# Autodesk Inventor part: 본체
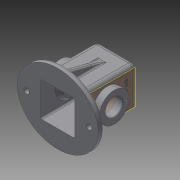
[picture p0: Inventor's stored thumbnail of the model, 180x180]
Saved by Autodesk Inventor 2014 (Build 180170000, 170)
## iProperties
Created: 2017-07
Part Number: 본체
Material: 일반
Document SubType Name: Modeling
Designer: 406-3333
Density: 1 g/cm^3
Appearance: 기본값
Author: 406-3333
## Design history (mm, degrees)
sketch "스케치1" dims "d0" = 65, "d1" = 75
  geometry: 2 further points; 1 other entity
  constraints: 1 coincident, 2 other
extrude "돌출1" new body sketch "스케치1" distance "d2" = 10; taper "d3" = 0 deg
sketch "스케치2"
  geometry: L1 (37, 37)-(-37, 37); L2 (-37, 37)-(-37, -37); L3 (-37, -37)-(37, -37); L4 (37, -37)-(37, 37); L5 (37, 37)-(-37, -37); L6 (-37, 37)-(37, -37); 1 further point; 1 other entity
  constraints: 12 end point, 2 midpoint, 2 parallel, 1 horizontal, 1 perpendicular, 1 other
  dimensions: "d4" = 74 distance between parallel lines of L4 L2; "d5" = 74 distance between parallel lines of L3 L1
extrude "돌출2" join sketch "스케치2" distance "d6" = 100; taper "d7" = 0 deg
node "작업 평면1"
sketch "스케치4"
  geometry: L1 (102, 0)-(102, -10) reference; L2 (102, -10)-(-28, -10) reference; L3 (-28, -10)-(-28, 0) reference; L4 (-28, 0)-(0, 0) reference; L5 (0, 0)-(0, 100) reference; L6 (0, 100)-(74, 100) reference; L7 (74, 100)-(74, 0) reference; L8 (74, 0)-(102, 0) reference; L9 (-18, 0)-(0, 72.194); L10 (74, 72.194)-(92, 0); L11 (-18, 0)-(0, 0); L12 (74, 72.194)-(74, 0); 1 further point
  constraints: 8 end point, 4 point on line, 1 collinear, 1 perpendicular
  dimensions: "d12" = 14 deg angle of L9 L3; "d13" = 14 deg angle of L1 L10; "d14" = 10 distance from line of L9.start L3; "d15" = 10 distance of L1.start L10.end
extrude "돌출4" join sketch "스케치4" stored distance "d16" = 10; taper "d17" = 0 deg
node "작업 평면2"
node "작업 평면4"
  node "작업 평면3"
sketch "스케치8"
  geometry: L1 (-11.448, 0)-(85.448, 0) reference; L2 (85.448, 0)-(85.448, -10) reference; L3 (85.448, -10)-(-11.448, -10) reference; L4 (-11.448, -10)-(-11.448, 0) reference; L5 (37, -10)-(37, 119.133); C1 r 27.5 at (37, 45)
  constraints: 2 end point, 1 centre point, 1 parallel, 1 point on line
  dimensions: "d29" = 55 distance from line of L3 C1.centre; "d30" = 55 diameter of C1
extrude "돌출8" join sketch "스케치8" distance "d31" = 100; taper "d32" = 0 deg
node "작업 평면5"
hole "구멍1" diameter "d45" = 32; stored, may be unused: countersink angle "d49" = 90 deg, drill point angle "d51" = 118 deg; dims "d43" = 10, "d44" = 10, "d46" = 6, "d47" = 4, "d48" = 2, "d50" = 8
sketch "스케치11" dims "d59" = 45
  geometry: L1 (0, 0)-(0, 47.659); C1 r 27.5 at (0, 0) reference; 3 further points
  constraints: 2 end point, 1 coincident, 1 point on line, 1 vertical, 1 vertical alignment, 2 other
hole "구멍3" sketch "스케치11" at (0, 22.5) diameter "d60" = 3.242; stored, may be unused: countersink angle "d64" = 90 deg, drill point angle "d66" = 118 deg; dims "d61" = 8, "d62" = 28, "d63" = 4, "d65" = 10
node "작업 평면6"
fillet "모깎기1" dims "d70" = 8
fillet "모깎기2" dims "d71" = 8
fillet "모깎기3" dims "d72" = 0.5
node "작업 평면7"
sketch "스케치12"
  geometry: L1 (20, 20)-(-20, 20); L2 (-20, 20)-(-20, -20); L3 (-20, -20)-(20, -20); L4 (20, -20)-(20, 20); L5 (20, 20)-(-20, -20); L6 (-20, 20)-(20, -20); 1 further point
  constraints: 12 end point, 2 midpoint, 2 parallel, 1 horizontal, 1 perpendicular
  dimensions: "d77" = 40 distance between parallel lines of L4 L2; "d78" = 40 distance between parallel lines of L3 L1
node "작업 평면8"
extrude "돌출10" join sketch "스케치12" distance "d84" = 10; taper "d85" = 0 deg
fillet "모깎기7" dims "d86" = 3
fillet "모깎기8" dims "d87" = 3
node "작업 평면9"
sketch "스케치14"
  geometry: 2 further points
  constraints: 1 coincident
hole "구멍4" sketch "스케치14" at (0, 0) diameter "d89" = 21; stored, may be unused: countersink angle "d93" = 90 deg, drill point angle "d95" = 118 deg; dims "d90" = 8, "d91" = 28, "d92" = 4, "d94" = 10
chamfer "모따기1" distance "d96" = 1; stored, may be unused: second distance "d97" = 2, angle "d98" = 5 deg
node "작업 평면10"
sketch "스케치15"
  geometry: L1 (12, 18)-(46, 18) reference; L2 (66, -92)-(66, 0) reference; 3 further points
  constraints: 1 other
  dimensions: "d101" = 30 distance from line of point (29, -12) L1; "d102" = 37 distance from line of L2 point (29, -12)
feature "엠보싱1" sketch "스케치15" dims "d103" = 0.5, "d104" = 0
fillet "모깎기10" dims "d105" = 3
fillet "모깎기11" dims "d106" = 3
fillet "모깎기12" dims "d107" = 3
sketch "스케치13"
  geometry: L1 (-72, 0)-(72, 0); L2 (-5, -37)-(-29, -37) reference; L3 (-37, -29)-(-37, 29) reference; L4 (-29, 37)-(-5, 37) reference; L5 (-5, 37)-(-5, 55) reference; L6 (-5, 55)-(5, 55) reference; L7 (5, 55)-(5, 37) reference; L8 (5, 37)-(29, 37) reference; L9 (37, 29)-(37, -29) reference; L10 (29, -37)-(5, -37) reference; L11 (5, -37)-(5, -55) reference; L12 (5, -55)-(-5, -55) reference; L13 (-5, -55)-(-5, -37) reference; C1 r 5 at (-58, 0); C2 r 5 at (58, 0); A1 r 8 centre (-29, -29) between (-37, -29) and (-29, -37) reference; A2 r 8 centre (-29, 29) between (-29, 37) and (-37, 29) reference; A3 r 8 centre (29, 29) between (37, 29) and (29, 37) reference; A4 r 8 centre (29, -29) between (29, -37) and (37, -29) reference; 2 further points; 1 other entity
  constraints: 2 centre point, 2 end point, 2 point on line, 1 other
  dimensions: "d80" = 58 distance of point (0, 0) C1.centre; "d81" = 58 distance of point (0, 0) C2.centre; "d82" = 10 diameter of C1; "d83" = 10 diameter of C2
extrude "돌출11" cut sketch "스케치13" stored distance "d108" = 10; taper "d109" = 0 deg
sketch "스케치16"
  geometry: L1 (32, 32)-(-32, 32); L2 (-32, 32)-(-32, -32); L3 (-32, -32)-(32, -32); L4 (32, -32)-(32, 32); L5 (32, 32)-(-32, -32); L6 (-32, 32)-(32, -32); C1 r 10.5 at (0, 0) reference; 1 further point; 1 other entity
  constraints: 12 end point, 2 midpoint, 2 parallel, 1 horizontal, 1 perpendicular, 1 other
  dimensions: "d110" = 64 distance of L3.end L2.end; "d111" = 64 distance of L2.end L1.end
extrude "돌출12" cut sketch "스케치16" distance "d112" = 105; taper "d113" = 0 deg
fillet "모깎기13" dims "d114" = 3
node "작업 평면11"
sketch "스케치17"
  geometry: L1 (-43, -92)-(-34, -92) reference; L2 (-34, -92)-(-34, -102) reference; L3 (-34, -102)-(-46, -102) reference; L4 (-46, -102)-(-46, -95) reference; L5 (104, -95)-(104, -102) reference; L6 (104, -102)-(92, -102) reference; L7 (92, -102)-(92, -92) reference; L8 (92, -92)-(101, -92) reference; L9 (68.026, -69.5)-(69, -71.121) reference; L10 (69, -71.121)-(79, -71.121) reference; L11 (79, -71.121)-(79, -74.5) reference; L12 (79, -74.5)-(66.5, -74.5) reference; L13 (66, -75)-(66, -89) reference; L14 (69, -92)-(82, -92) reference; L15 (82, -92)-(82, -102) reference; L16 (82, -102)-(61, -102) reference; L17 (61, -102)-(61, -63) reference; L18 (61, -63)-(78, -63) reference; L19 (78, -63)-(79, -64) reference; L20 (79, -64)-(79, -67.879) reference; L21 (79, -67.879)-(69, -67.879) reference; L22 (69, -67.879)-(68.026, -69.5) reference; L23 (69, -22.879)-(68.026, -24.5) reference; L24 (68.026, -24.5)-(69, -26.121) reference; L25 (69, -26.121)-(79, -26.121) reference; L26 (79, -26.121)-(79, -30) reference; L27 (79, -30)-(78, -31) reference; L28 (78, -31)-(61, -31) reference; L29 (61, -31)-(61, 0) reference; L30 (58, 3)-(39.5, 3) reference; L31 (39.5, 3)-(39.5, 14) reference; L32 (39.5, 14)-(43, 14) reference; L33 (43, 14)-(43, 18) reference; L34 (43, 18)-(49, 18) reference; L35 (49, 18)-(49, 11) reference; L36 (52, 8)-(58, 8) reference; L37 (66, 0)-(66, -9.615) reference; L38 (66, -9.615)-(66.5, -9.615) reference; L39 (66.5, -9.615)-(66.5, -10.029) reference; L40 (66.5, -10.029)-(66, -10.029) reference; L41 (66, -10.029)-(66, -19) reference; L42 (66.5, -19.5)-(79, -19.5) reference; L43 (79, -19.5)-(79, -22.879) reference; L44 (79, -22.879)-(69, -22.879) reference; L45 (-11, -71.121)-(-10.026, -69.5) reference; L46 (-10.026, -69.5)-(-11, -67.879) reference; L47 (-11, -67.879)-(-21, -67.879) reference; L48 (-21, -67.879)-(-21, -64) reference; L49 (-21, -64)-(-20, -63) reference; L50 (-20, -63)-(-3, -63) reference; L51 (-3, -63)-(-3, -102) reference; L52 (-3, -102)-(-24, -102) reference; L53 (-24, -102)-(-24, -92) reference; L54 (-24, -92)-(-11, -92) reference; L55 (-8, -89)-(-8, -75) reference; L56 (-8.5, -74.5)-(-21, -74.5) reference; L57 (-21, -74.5)-(-21, -71.121) reference; L58 (-21, -71.121)-(-11, -71.121) reference; L59 (-10.026, -24.5)-(-11, -22.879) reference; L60 (-11, -22.879)-(-21, -22.879) reference; L61 (-21, -22.879)-(-21, -19.5) reference; L62 (-21, -19.5)-(-8.5, -19.5) reference; L63 (-8, -19)-(-8, 0) reference; L64 (0, 8)-(6, 8) reference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; A1 r 0.5 centre (66.5, -75) between (66.5, -74.5) and (66, -75) reference; A2 r 3 centre (69, -89) between (66, -89) and (69, -92) reference; A3 r 3 centre (58, 0) between (61, 0) and (58, 3) reference; A4 r 3 centre (52, 11) between (49, 11) and (52, 8) reference; A5 r 8 centre (58, 0) between (66, 0) and (58, 8) reference; A6 r 0.5 centre (66.5, -19) between (66, -19) and (66.5, -19.5) reference; A7 r 3 centre (-11, -89) between (-11, -92) and (-8, -89) reference; A8 r 0.5 centre (-8.5, -75) between (-8, -75) and (-8.5, -74.5) reference; A9 r 0.5 centre (-8.5, -19) between (-8.5, -19.5) and (-8, -19) reference; A10 r 8 centre (0, 0) between (0, 8) and (-8, 0) reference; A11 r 3 centre (6, 11) between (6, 8) and (9, 11) reference; A12 r 3 centre (0, 0) between (0, 3) and (-3, 0) reference
  constraints: 39 end point, 8 perpendicular, 8 point on line, 7 parallel, 3 point on circle, 3 symmetric about line, 1 midpoint, 2 other
revolve "회전1" sketch "스케치17" stored, may be unused: angle "d118" = 90 deg
sketch "스케치18"
  geometry: C1 r 16 at (0, 0) reference; C2 r 16 at (0, 0); 1 further point
  constraints: 1 centre point, 1 coincident
  dimensions: "d119" = 32 diameter of C2
extrude "돌출13" cut sketch "스케치18" stored distance "d120" = 105; taper "d121" = 0 deg
fillet "모깎기14" dims "d122" = 3
fillet "모깎기15" dims "d123" = 0.5
node "솔리드1"
pattern_circular "원형 패턴1" dims angle "d68" = 360 deg
mirror "대칭1"
node "절단 모서리 투영1"
node "절단 모서리 투영5"
node "절단 모서리 투영7"
node "절단 모서리 투영8"
other parameters: "d33" = 32, "d34" = 32, "d36" = 7, "d39" = 135 deg, "d40" = 135 deg, "d76" = 0, "d79" = 0, "d88" = 0, "d100" = 0, "d115" = 27.5, "d116" = 27.5, "d117" = 7
